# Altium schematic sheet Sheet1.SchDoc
size A3; SheetNumber: 1; SheetTotal: 1
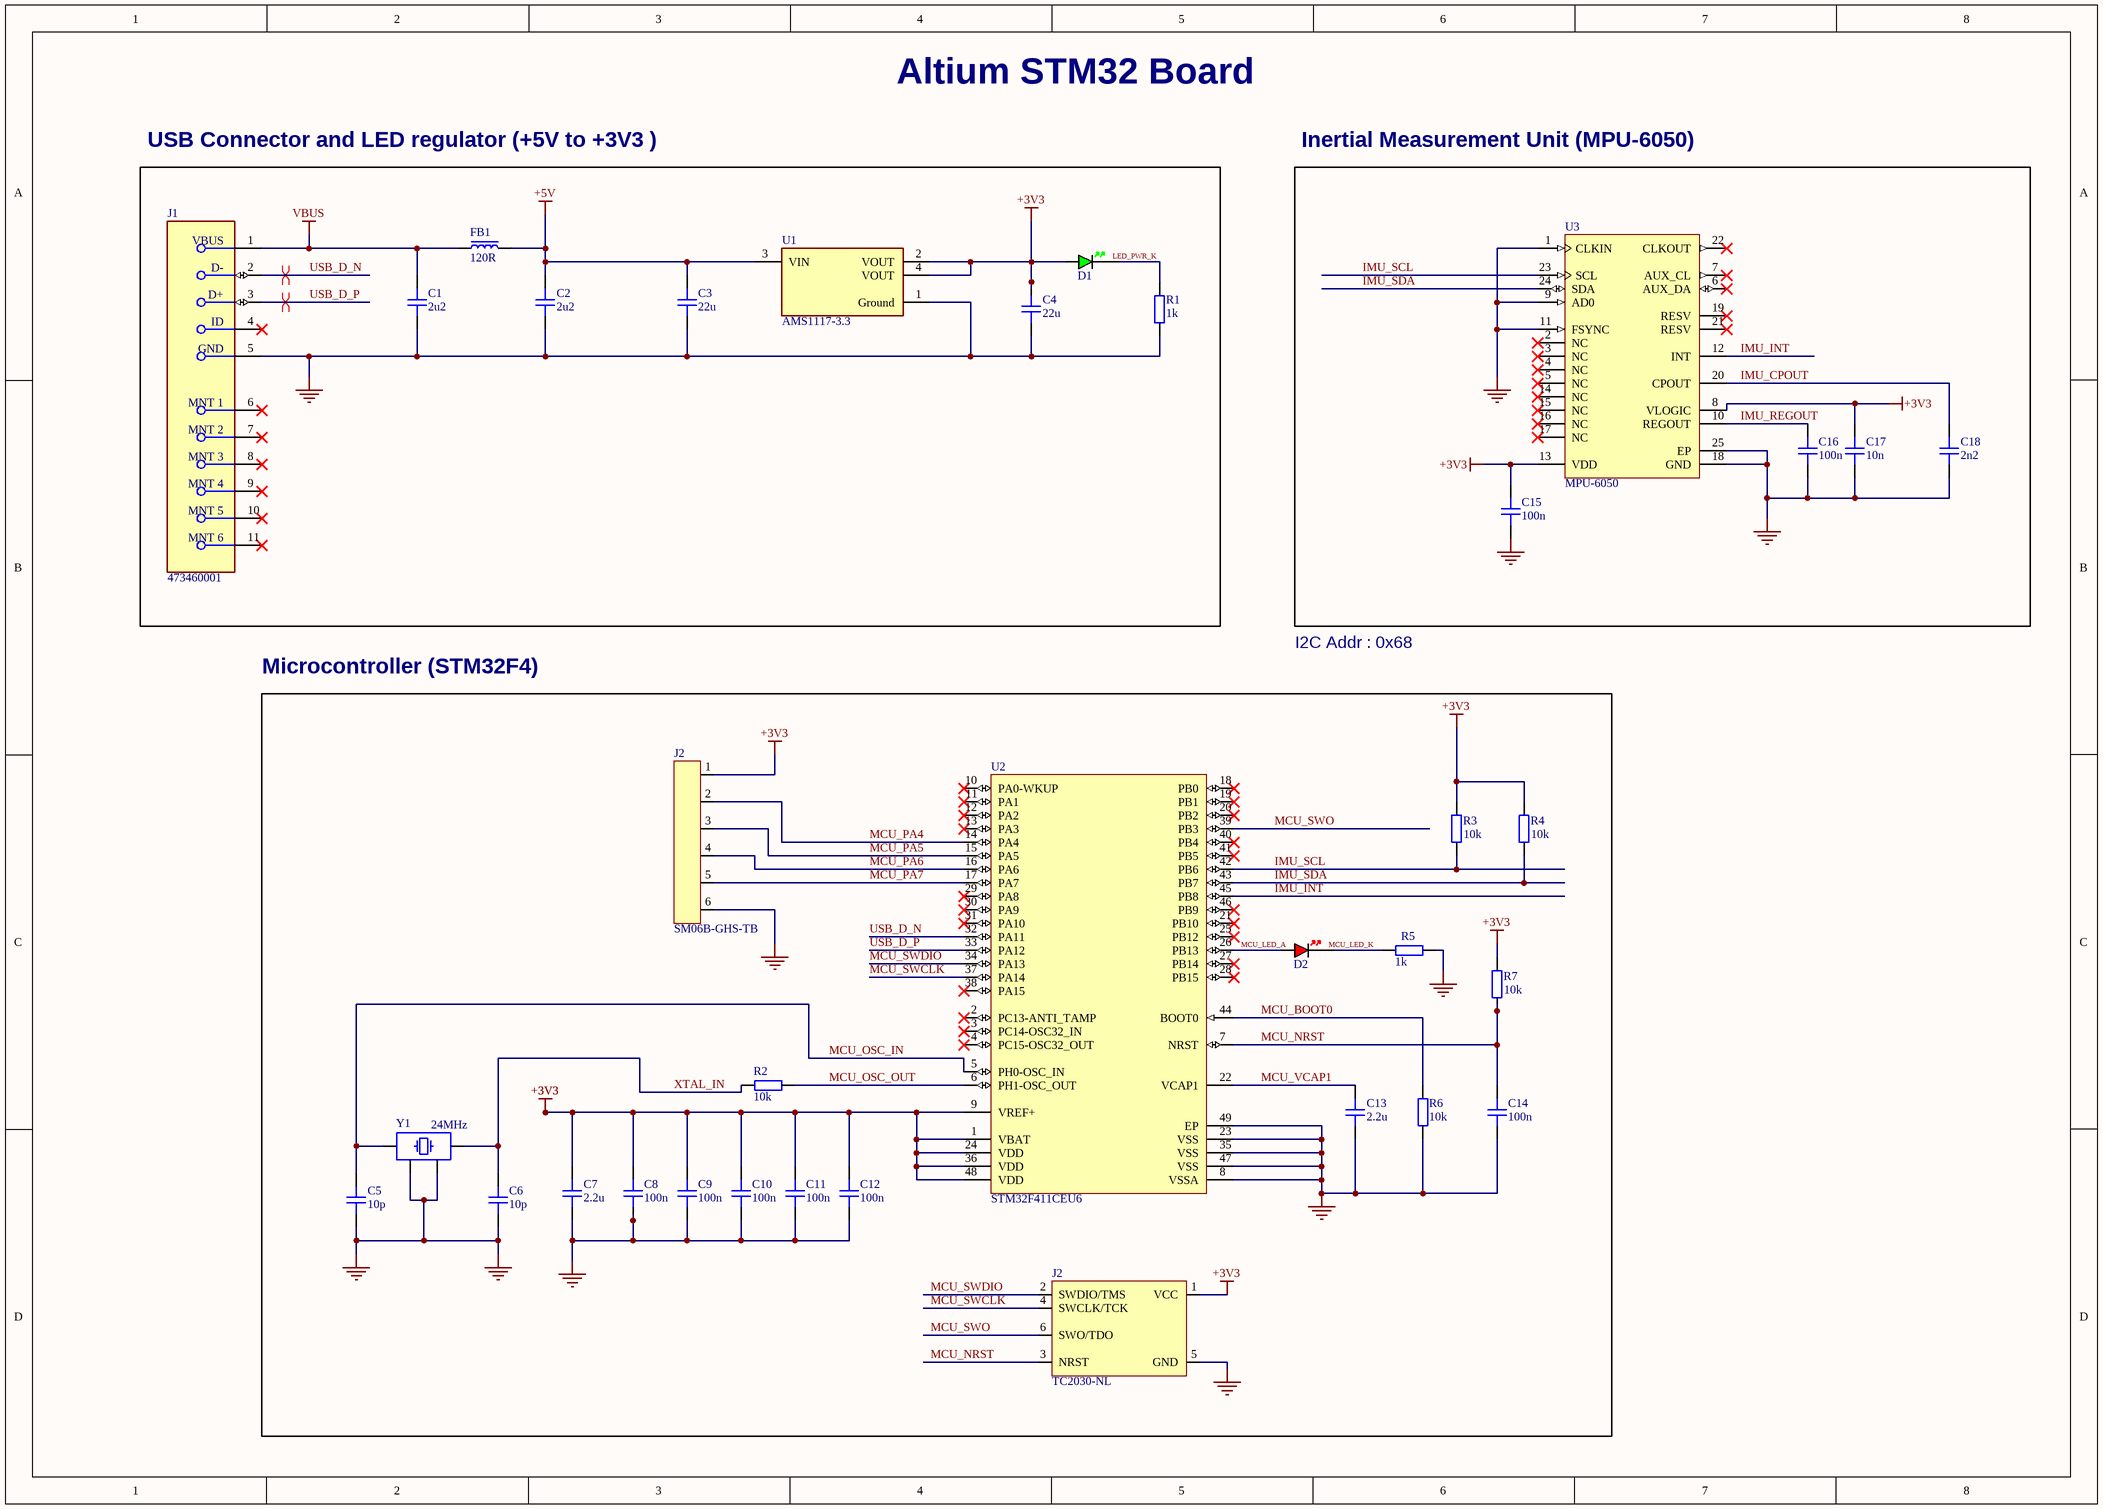
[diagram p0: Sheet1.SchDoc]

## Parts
(Parts that share a designator on the sheet are numbered #1, #2 ... from top to bottom, then left to right.)
C1  2u2  [CAP_0402]
C2  2u2  [CAP_0402]
C3  22u  [CAP_0402]
C4  22u  [CAP_0402]
C5  10p  [CAP_0402]
C6  10p  [CAP_0402]
C7  2.2u  [CAP_0603]
C8  100n  [CAP_0402]
C9  100n  [CAP_0402]
C10  100n  [CAP_0402]
C11  100n  [CAP_0402]
C12  100n  [CAP_0402]
C13  2.2u  [CAP_0603]
C14  100n  [CAP_0402]
C15  100n  [CAP_0402]
C16  100n  [CAP_0402]
C17  10n  [CAP_0402]
C18  2n2  [CAP_0402]
D1  GREEN  [LED_0402_GREEN]  (value not drawn)
D2  RED  [LED_0402_RED]  (value not drawn)
FB1  120R  [FB_0603]
J1  473460001  [FP-473460001-MFG]
J2#1  SM06B-GHS-TB  [SM06B-GHS-TB]
J2#2  TC2030-NL  [TC2030-NL-FP]  (no BOM)
R1  1k  [RES_0402]
R2  10k  [RES_0402]
R3  10k  [RES_0402]
R4  10k  [RES_0402]
R5  1k  [RES_0402]
R6  10k  [RES_0402]
R7  10k  [RES_0402]
U1  AMS1117-3.3  [FP-ams1117-IPC_C]
U2  STM32F411CEU6  [STM-UFQFPN48_L]
U3  MPU-6050  [IS-QFN-24_V]
Y1  24MHz  [XTAL_3225]

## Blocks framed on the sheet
USB Connector and LED regulator (+5V to +3V3 ): C1-C4 D1 FB1 J1 R1 U1
Inertial Measurement Unit (MPU-6050): C15-C18 U3
Microcontroller (STM32F4): C5-C14 D2 J2#1 J2#2 R2-R7 U2 Y1

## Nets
+3V3: C4.1 C7.2 C8.1 C9.1 C10.1 C11.1 C12.1 C15.1 C17.1 D1.A J2#1.1 J2#2.1(VCC) R3.2 R4.2 R7.2 U1.2(VOUT) U1.4(VOUT) U2.1(VBAT) U2.9(VREF+) U2.24(VDD) U2.36(VDD) U2.48(VDD) U3.8(VLOGIC) U3.13(VDD)
+5V: C2.1 C3.1 FB1.2 U1.3(VIN)
GND: C1.2 C2.2 C3.2 C4.2 C5.1 C6.1 C7.1 C8.2 C9.2 C10.2 C11.2 C12.2 C13.1 C14.2 C15.2 C16.2 C17.2 C18.2 J1.5(GND) J2#1.6 J2#2.5(GND) R1.1 R5.1 R6.1 U1.1(Ground) U2.8(VSSA) U2.23(VSS) U2.35(VSS) U2.47(VSS) U2.49(EP) U3.1(CLKIN) U3.9(AD0) U3.11(FSYNC) U3.18(GND) U3.25(EP) Y1.2 Y1.4
VBUS: C1.1 FB1.1 J1.1(VBUS)
IMU_CPOUT: C18.1 U3.20(CPOUT)
IMU_INT: U2.45(PB8) U3.12(INT)
IMU_REGOUT: C16.1 U3.10(REGOUT)
IMU_SCL: R3.1 U2.42(PB6) U3.23(SCL)
IMU_SDA: R4.1 U2.43(PB7) U3.24(SDA)
MCU_BOOT0: R6.2 U2.44(BOOT0)
MCU_LED_A: D2.A U2.26(PB13)
MCU_NRST: C14.1 J2#2.3(NRST) R7.1 U2.7(NRST)
MCU_OSC_IN: C5.2 U2.5(PH0-OSC_IN) Y1.1
MCU_OSC_OUT: R2.1 U2.6(PH1-OSC_OUT)
MCU_PA4: J2#1.2 U2.14(PA4)
MCU_PA5: J2#1.3 U2.15(PA5)
MCU_PA6: J2#1.4 U2.16(PA6)
MCU_PA7: J2#1.5 U2.17(PA7)
MCU_SWCLK: J2#2.4(SWCLK/TCK) U2.37(PA14)
MCU_SWDIO: J2#2.2(SWDIO/TMS) U2.34(PA13)
MCU_SWO: J2#2.6(SWO/TDO) U2.39(PB3)
MCU_VCAP1: C13.2 U2.22(VCAP1)
USB_D_N: J1.2(D-) U2.32(PA11)
USB_D_P: J1.3(D+) U2.33(PA12)
XTAL_IN: C6.2 R2.2 Y1.3
NetD1_K: D1.K R1.2
NetD2_K: D2.K R5.2

Not connected (* = marked no-connect by the designer): J1 4(ID)* 6(MNT_1)* 7(MNT_2)* 8(MNT_3)* 9(MNT_4)* 10(MNT_5)* 11(MNT_6)*; U2 2(PC13-ANTI_TAMP)* 3(PC14-OSC32_IN)* 4(PC15-OSC32_OUT)* 10(PA0-WKUP)* 11(PA1)* 12(PA2)* 13(PA3)* 18(PB0)* 19(PB1)* 20(PB2)* 21(PB10)* 25(PB12)* 27(PB14)* 28(PB15)* 29(PA8)* 30(PA9)* 31(PA10)* 38(PA15)* 40(PB4)* 41(PB5)* 46(PB9)*; U3 2(NC)* 3(NC)* 4(NC)* 5(NC)* 6(AUX_DA)* 7(AUX_CL)* 14(NC)* 15(NC)* 16(NC)* 17(NC)* 19(RESV)* 21(RESV)* 22(CLKOUT)*

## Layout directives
differential pair: USB_D_N, USB_D_P

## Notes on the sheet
- Altium STM32 Board
- I2C Addr : 0x68
- Labels drawn without touching a wire or pin: LED_PWR_K, MCU_LED_K

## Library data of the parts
C1-C6 C8-C12 C14-C18 = CAP_0402: Capacitor SMD 0402
C7 C13 = CAP_0603: Capacitor SMD 0603
D1 = LED_0402_GREEN: LED 0402 GREEN SMD
D2 = LED_0402_RED: LED 0402 RED SMD
FB1 = FB_0603: Ferrite Bead SMD 0603
J1 = CMP-2000-05246-2: CONN RCPT USB2.0 MICRO B SMD R/A; Manufacturer: Molex; Conn Orientation: Right Angle; Is Female: yes; Shielding: true; Pitch: 0.65mm; Number Of Contacts: 5; Description: USB - micro B USB 2.0 Receptacle Connector 5 Position Surface Mount, Right Angle; Voltage Rating: 30V; Current Rating: 1.8A
J2#1 = SM06B-GHS-TB: Header Connector 6 Position 1.25MM Pitch SMD Horizontal JST GH
J2#2 = TC2030-NL: Tag-Connect No-Solder SWD Debug Connector (No Legs) DO NOT PLACE
R1-R7 = RES_0402: Resistor SMD 0402
U1 = CMP-209535-000002-1: 1A LOW DROPOUT VOLTAGE REGULATOR
U2 = CMP-0243-00165-1: ARM Cortex-M4 32-bit MCU+FPU, 512 KB Flash, 128 KB RAM, 36 I/Os, 48-Pin UFQFPN, -40 to 85 degC, Tray; Operating Frequency(F) (Processor speed) (MHz): 100; FLASH Size (Prog) (kB): 512; Internal RAM Size (kB): 128; I/Os (High Current): 36; Supply Voltage(Vcc) min (V): 1.7
U3 = CMP-1753-00002-2: 3-Axis Gyroscope, Accelerometer and a Digital Motion Processor(TM) (DMP), 2.375 to 3.46 V, -40 to 85 degC, 24-Pin QFN, RoHS, Tape and Reel; Manufacturer: InvenSense; Featured Product: MPU-60506-Axis,IntegratedI²CSolution; Other Names: 1428-1007-2 / MPU6050; Sensor Type: MotionTracking; Online Catalog: MPU-6000™Series
Y1 = TSX-3225_24.0000MF15X-AC: Crystal SMD 24MHz 10PPM 7pF 3225; Manufacturer: Epson; Manufacturer Part Number: TSX-3225 24.0000MF15X-AC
